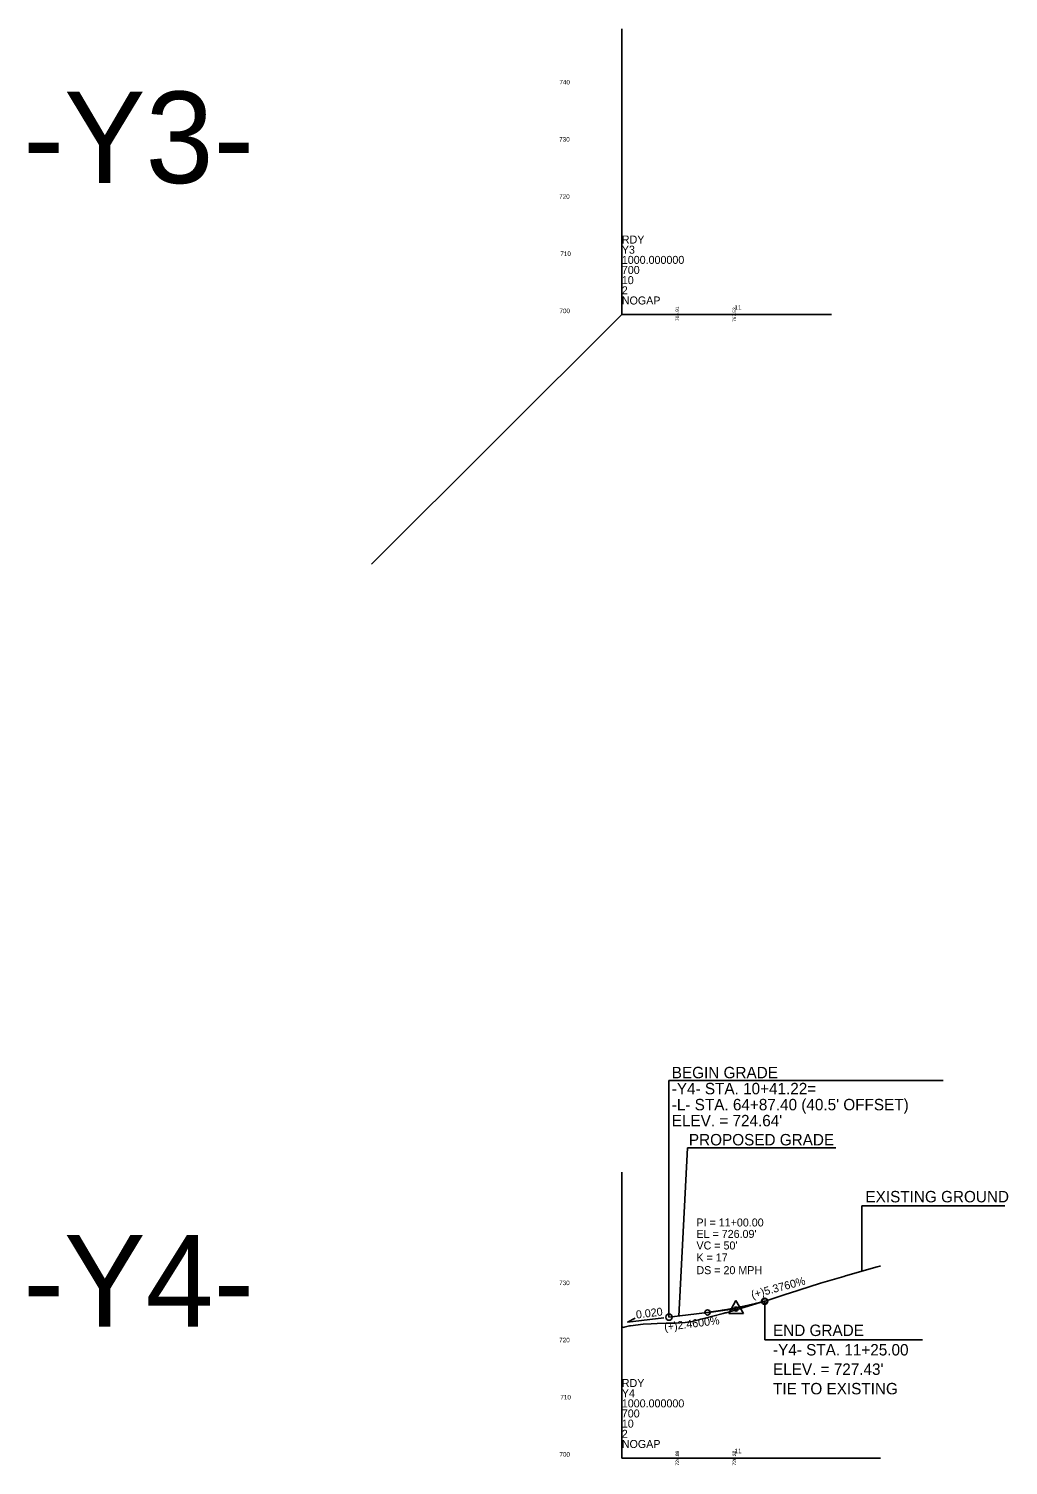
# Model space of a CAD drawing. Extents: x 1554255 to 1803987, y 659549 to 692876.
# Drawn here: x 1554284 to 1555141, y 688303 to 689559 of the extents above; entities that cross this region are included whole.
import ezdxf

# ---------------------------------------------------------------- set-up
doc = ezdxf.new("R2010")
doc.units = 0
for name, color, linetype in [('Default', 7, 'Continuous'), ('Exist Profile Cell', 7, 'Continuous'), ('Exist Vertical Profile Ground Line', 7, 'Continuous'), ('Exist Vertical Profile Vertical Axis Label', 7, 'Continuous'), ('Prop PFL Text', 7, 'Continuous'), ('Prop PFL VPI Symbol CELL', 7, 'Continuous'), ('Prop Vertical Profile Curve Label', 7, 'Continuous'), ('Prop Vertical Profile Grade', 7, 'Continuous'), ('Prop Vertical Profile Grade Label', 7, 'Continuous'), ('Prop Vertical Profile Strip Grade', 7, 'Continuous'), ('Prop VPI Label', 7, 'Continuous')]:
    doc.layers.add(name, color=color, linetype=linetype)

msp = doc.modelspace()

# ---------------------------------------------------------------- linework, layer by layer
at = {"layer": 'Default'}
msp.add_line((1554802.9, 689309.3), (1554584, 689091), dxfattribs=at)
at = {"layer": 'Exist Profile Cell'}
for p, q in [((1554802.9, 689309.3), (1554802.9, 689559.3)), ((1554802.9, 689309.3), (1554986.5, 689309.3)), ((1554802.9, 689309.3), (1554802.9, 689309.3)), ((1554802.9, 688309.3), (1554802.9, 688559.3)), ((1554802.9, 688309.3), (1555029.3, 688309.3)), ((1554802.9, 688309.3), (1554802.9, 688309.3))]:
    msp.add_line(p, q, dxfattribs=at)
at = {"layer": 'Exist Vertical Profile Ground Line'}
msp.add_lwpolyline([(1554802.9, 688423.7), (1554803.7, 688423.7), (1554804.1, 688423.6), (1554804.9, 688423.8), (1554809.5, 688424.8), (1554810.4, 688424.9), (1554821.5, 688426.5), (1554828.7, 688426.8), (1554833.8, 688427), (1554842.4, 688427.2), (1554846.2, 688427.3), (1554849.3, 688427.2), (1554858.4, 688427.8), (1554862.5, 688428.4), (1554863.3, 688428.5), (1554864.5, 688428.8), (1554891.5, 688435.6), (1554893.4, 688436.2), (1554894.2, 688436.3), (1554900, 688438), (1554927.8, 688446.4), (1554930, 688447), (1554947.5, 688452.8), (1554948.8, 688453.2), (1554976.8, 688462.3), (1554978.8, 688462.9), (1554997.2, 688468.2), (1554998.6, 688468.6), (1555026.4, 688476.6), (1555028.6, 688477.2), (1555029.3, 688477.2)], dxfattribs=at)
at = {"layer": 'Prop PFL Text'}
for p, q in [((1555084, 688639.4), (1554844.1, 688639.4)), ((1554844.1, 688432.5), (1554844.1, 688639.4)), ((1554852.8, 688433.5), (1554860.3, 688580.5)), ((1554990.2, 688580.5), (1554860.3, 688580.5)), ((1555138.1, 688529.9), (1555012.8, 688529.9)), ((1555012.8, 688529.9), (1555012.8, 688472.7)), ((1554927.9, 688412.8), (1554927.9, 688446.4)), ((1555066.1, 688412.8), (1554927.9, 688412.8))]:
    msp.add_line(p, q, dxfattribs=at)
at = {"layer": 'Prop PFL VPI Symbol CELL'}
for p, q in [((1554902.8, 688447), (1554896.4, 688435.8)), ((1554902.8, 688447), (1554909.3, 688435.8)), ((1554896.4, 688435.8), (1554909.3, 688435.8))]:
    msp.add_line(p, q, dxfattribs=at)
for radius in [1.75, 1.2]:
    msp.add_circle((1554902.8, 688439.6), radius, dxfattribs=at)
at = {"layer": 'Prop Vertical Profile Curve Label'}
for centre in [(1554927.9, 688446.4), (1554877.9, 688436.6)]:
    msp.add_circle(centre, 2.25, dxfattribs=at)
at = {"layer": 'Prop Vertical Profile Grade'}
msp.add_line((1554844.1, 688432.5), (1554877.9, 688436.6), dxfattribs=at)
msp.add_spline([(1554877.9, 688436.6), (1554878.9, 688436.7), (1554879.9, 688436.9), (1554880.9, 688437), (1554881.9, 688437.1), (1554882.9, 688437.3), (1554883.9, 688437.4), (1554884.9, 688437.5), (1554885.9, 688437.7), (1554886.9, 688437.8), (1554887.9, 688438), (1554888.9, 688438.1), (1554889.9, 688438.3), (1554890.9, 688438.5), (1554891.9, 688438.6), (1554892.9, 688438.8), (1554893.9, 688439), (1554894.9, 688439.1), (1554895.9, 688439.3), (1554896.9, 688439.5), (1554897.9, 688439.7), (1554898.9, 688439.8), (1554899.9, 688440), (1554900.9, 688440.2), (1554901.9, 688440.4), (1554902.9, 688440.6), (1554903.9, 688440.8), (1554904.9, 688441), (1554905.9, 688441.2), (1554906.9, 688441.4), (1554907.9, 688441.6), (1554908.9, 688441.8), (1554909.9, 688442), (1554910.9, 688442.3), (1554911.9, 688442.5), (1554912.9, 688442.7), (1554913.9, 688442.9), (1554914.9, 688443.2), (1554915.9, 688443.4), (1554916.9, 688443.6), (1554917.9, 688443.9), (1554918.9, 688444.1), (1554919.9, 688444.4), (1554920.9, 688444.6), (1554921.9, 688444.8), (1554922.9, 688445.1), (1554923.9, 688445.4), (1554924.9, 688445.6), (1554925.9, 688445.9), (1554926.9, 688446.1), (1554927.9, 688446.4)], degree=3, dxfattribs=at)
at = {"layer": 'Prop VPI Label'}
for p, q in [((1554927.9, 688446.4), (1554905.5, 688440.4)), ((1554839.7, 688432), (1554807.9, 688428.1)), ((1554807.9, 688428.1), (1554814.7, 688431.7)), ((1554877.9, 688436.6), (1554900.1, 688439.4))]:
    msp.add_line(p, q, dxfattribs=at)
for centre in [(1554927.9, 688446.4), (1554844.1, 688432.5)]:
    msp.add_circle(centre, 2.75, dxfattribs=at)

# ---------------------------------------------------------------- texts
at = {"layer": 'Default'}
for s, p in [('740', (1554748.3, 689510.5)), ('730', (1554748.1, 689460.5)), ('720', (1554748.1, 689410.5)), ('710', (1554749.1, 689360.5)), ('700', (1554748.3, 689310.5)), ('11', (1554901.5, 689313.5)), ('730', (1554748.1, 688460.5)), ('720', (1554748.1, 688410.5)), ('710', (1554749.1, 688360.5)), ('11', (1554901.5, 688313.5)), ('700', (1554748.3, 688310.5))]:
    msp.add_text(s, height=4, dxfattribs=at).set_placement(p)
at = {"layer": 'Exist Profile Cell'}
for s, p in [('RDY', (1554802.9, 689371.4)), ('Y3', (1554802.9, 689362.5)), ('1000.000000', (1554802.9, 689353.6)), ('700', (1554802.9, 689344.8)), ('2', (1554802.9, 689327)), ('10', (1554802.9, 689335.9)), ('NOGAP', (1554802.9, 689318.1)), ('RDY', (1554802.9, 688371.4)), ('Y4', (1554802.9, 688362.5)), ('1000.000000', (1554802.9, 688353.6)), ('700', (1554802.9, 688344.8)), ('10', (1554802.9, 688335.9)), ('2', (1554802.9, 688327)), ('NOGAP', (1554802.9, 688318.1))]:
    msp.add_text(s, height=7, dxfattribs=at).set_placement(p)
at = {"layer": 'Exist Vertical Profile Vertical Axis Label'}
for s, p in [('-Y3-', (1554279.2, 689424.3)), ('-Y4-', (1554279.2, 688424.3))]:
    msp.add_text(s, height=80, dxfattribs=at).set_placement(p)
at = {"layer": 'Prop PFL Text'}
for s, p in [('BEGIN GRADE', (1554846.6, 688641.4)), ('-Y4- STA. 10+41.22=', (1554846.6, 688627.4)), ("-L- STA. 64+87.40 (40.5' OFFSET)", (1554846.6, 688613.4)), ("ELEV. = 724.64'", (1554846.6, 688599.4)), ('PROPOSED GRADE', (1554861.6, 688582.7)), ('EXISTING GROUND', (1555016.1, 688532.9)), ('END GRADE', (1554935.2, 688416)), ('-Y4- STA. 11+25.00', (1554935.2, 688399)), ("ELEV. = 727.43'", (1554935.2, 688382)), ('TIE TO EXISTING', (1554935.2, 688365))]:
    msp.add_text(s, height=10, rotation=360, dxfattribs=at).set_placement(p)
at = {"layer": 'Prop Vertical Profile Grade Label'}
for s, rotation, p in [('(+)5.3760%', 15.0456, (1554917.1, 688448.6)), ('0.020', 7.0007, (1554815.7, 688431.2)), ('(+)2.4600%', 7.0122, (1554840.4, 688420.4))]:
    msp.add_text(s, height=7, rotation=rotation, dxfattribs=at).set_placement(p)
at = {"layer": 'Prop Vertical Profile Strip Grade'}
for s, p in [('765.91', (1554852.9, 689303.6)), ('765.91', (1554852.9, 689303.6)), ('767.53', (1554902.9, 689302.9)), ('767.52', (1554902.9, 689302.9)), ('724.86', (1554852.9, 688302.9)), ('724.86', (1554852.9, 688302.9)), ('724.82', (1554852.9, 688302.8)), ('724.82', (1554852.9, 688302.8)), ('724.82', (1554852.9, 688302.8)), ('724.82', (1554852.9, 688302.8)), ('726.24', (1554902.9, 688302.8)), ('726.24', (1554902.9, 688302.8)), ('726.24', (1554902.9, 688302.8)), ('726.24', (1554902.9, 688302.8)), ('726.27', (1554902.9, 688302.9)), ('726.27', (1554902.9, 688302.9))]:
    msp.add_text(s, height=3, rotation=90, dxfattribs=at).set_placement(p)
at = {"layer": 'Prop VPI Label'}
for s, p in [('PI = 11+00.00', (1554868.2, 688511.8)), ("EL = 726.09'", (1554868.2, 688501.8)), ("VC = 50'", (1554868.2, 688491.7)), ('K = 17', (1554868.2, 688481.2)), ('DS = 20 MPH', (1554868.2, 688470.1))]:
    msp.add_text(s, height=7, dxfattribs=at).set_placement(p)

doc.saveas('drawing.dxf')
